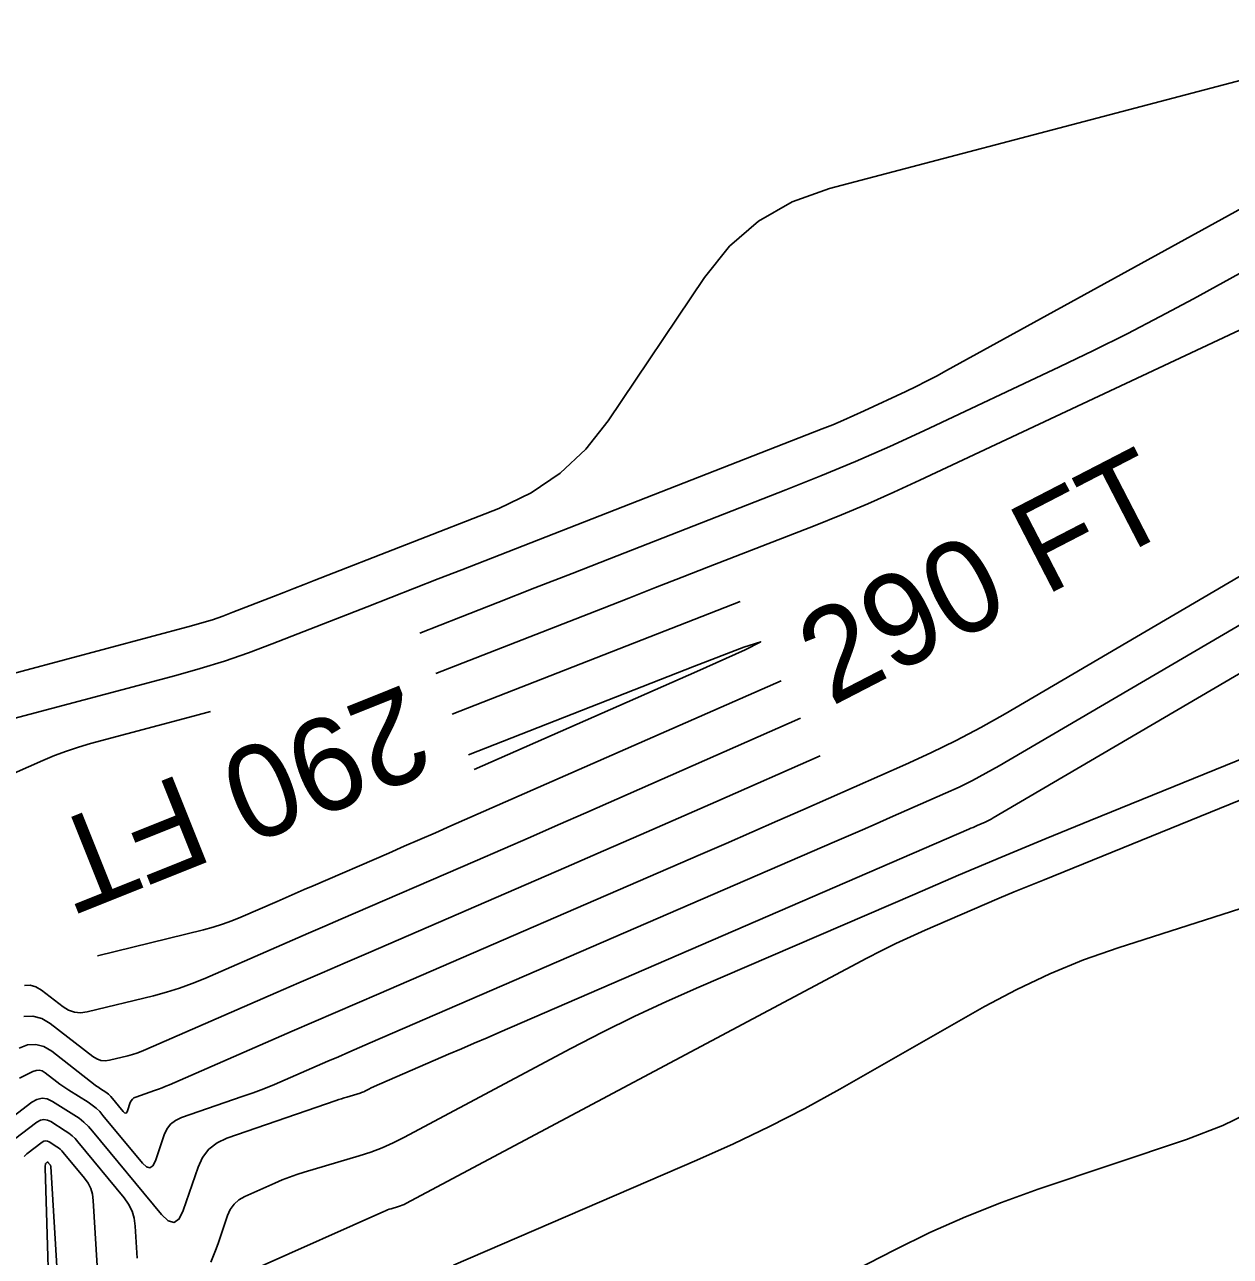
# Model space of a CAD drawing. Extents: x 1768942 to 1774819, y 723037 to 732099.
# Drawn here: x 1771159.5 to 1771237.8, y 724938 to 725018 of the extents above; entities that cross this region are included whole.
import ezdxf

# ---------------------------------------------------------------- set-up
doc = ezdxf.new("R2010")
doc.units = 0
doc.layers.add('R_Contour Annot', color=7, linetype='Continuous')
doc.layers.add('R_Contours', color=7, linetype='Continuous')

msp = doc.modelspace()

# ---------------------------------------------------------------- linework, layer by layer
at = {"layer": 'R_Contours'}
for points in [[(1771252.283, 725017.976), (1771211.803, 725007.343), (1771209.362, 725006.474), (1771207.194, 725005.222), (1771205.298, 725003.586), (1771203.675, 725001.567), (1771197.412, 724992.252), (1771195.972, 724990.415), (1771194.311, 724988.856), (1771192.426, 724987.574), (1771190.32, 724986.569), (1771178.334, 724981.891), (1771177.673, 724981.633), (1771177.013, 724981.375), (1771176.352, 724981.117), (1771175.692, 724980.858), (1771173.05, 724979.825), (1771172.387, 724979.576), (1771171.717, 724979.346), (1771171.041, 724979.135), (1771170.359, 724978.942), (1771153.855, 724974.542)], [(1771158.833, 724972.923), (1771169.339, 724975.724), (1771170.928, 724976.172), (1771172.503, 724976.664), (1771174.063, 724977.2), (1771175.609, 724977.78), (1771181.763, 724980.188), (1771183.302, 724980.79), (1771184.841, 724981.392), (1771186.38, 724981.993), (1771187.919, 724982.594), (1771211.322, 724991.729), (1771212.013, 724992.005), (1771212.699, 724992.293), (1771213.38, 724992.592), (1771214.056, 724992.903), (1771216.752, 724994.169), (1771217.423, 724994.491), (1771218.089, 724994.823), (1771218.749, 724995.166), (1771219.405, 724995.519), (1771255.159, 725015.181)], [(1771254.458, 725010.646), (1771235.427, 725000.181), (1771233.283, 724999.024), (1771231.121, 724997.902), (1771228.942, 724996.814), (1771226.744, 724995.761), (1771217.921, 724991.617), (1771215.707, 724990.599), (1771213.477, 724989.619), (1771211.231, 724988.677), (1771208.968, 724987.772), (1771197.504, 724983.297), (1771195.086, 724982.354), (1771192.669, 724981.409), (1771190.252, 724980.464), (1771187.835, 724979.518), (1771185.181, 724978.48)], [(1771239.857, 724998.818), (1771217.665, 724988.395), (1771215.981, 724987.621), (1771214.285, 724986.876), (1771212.576, 724986.159), (1771210.856, 724985.471), (1771203.949, 724982.775), (1771202.223, 724982.101), (1771200.496, 724981.427), (1771198.77, 724980.752), (1771197.044, 724980.077), (1771186.235, 724975.846)], [(1771156.227, 724945.148), (1771159.995, 724948.02), (1771160.323, 724948.209), (1771160.657, 724948.283), (1771160.995, 724948.24), (1771161.339, 724948.08), (1771162.725, 724947.21), (1771163.061, 724946.98), (1771163.375, 724946.726), (1771163.668, 724946.447), (1771163.939, 724946.144), (1771168.41, 724940.73), (1771168.852, 724940.317), (1771169.237, 724940.223), (1771169.563, 724940.448), (1771169.831, 724940.99), (1771170.786, 724943.798), (1771171.083, 724944.442), (1771171.495, 724944.971), (1771172.022, 724945.386), (1771172.665, 724945.686), (1771179.757, 724948.137), (1771179.928, 724948.195), (1771180.099, 724948.251), (1771180.271, 724948.305), (1771180.443, 724948.357), (1771181.321, 724948.619), (1771181.4, 724948.645), (1771181.477, 724948.674), (1771181.553, 724948.708), (1771181.627, 724948.745), (1771181.921, 724948.901), (1771181.995, 724948.939), (1771182.069, 724948.976), (1771182.144, 724949.011), (1771182.22, 724949.045), (1771187.062, 724951.132), (1771187.894, 724951.491), (1771188.726, 724951.85), (1771189.558, 724952.21), (1771190.39, 724952.57), (1771220.852, 724965.75), (1771220.984, 724965.807), (1771221.117, 724965.865), (1771221.249, 724965.923), (1771221.381, 724965.981), (1771221.909, 724966.213), (1771222.04, 724966.273), (1771222.169, 724966.336), (1771222.296, 724966.403), (1771222.422, 724966.474), (1771261.237, 724989.205)], [(1771159.189, 724949.581), (1771160.055, 724950.015), (1771160.266, 724950.091), (1771160.471, 724950.103), (1771160.67, 724950.051), (1771160.862, 724949.936), (1771161.62, 724949.347), (1771161.811, 724949.202), (1771162.006, 724949.062), (1771162.204, 724948.927), (1771162.405, 724948.797), (1771163.65, 724948.016), (1771163.917, 724947.833), (1771164.166, 724947.631), (1771164.399, 724947.41), (1771164.614, 724947.169), (1771167.172, 724944.072), (1771167.435, 724943.826), (1771167.664, 724943.77), (1771167.858, 724943.903), (1771168.018, 724944.226), (1771168.587, 724945.898), (1771168.763, 724946.281), (1771169.008, 724946.596), (1771169.322, 724946.843), (1771169.705, 724947.022), (1771173.649, 724948.385), (1771174.357, 724948.637), (1771175.06, 724948.903), (1771175.758, 724949.183), (1771176.451, 724949.477), (1771179.21, 724950.679), (1771179.9, 724950.979), (1771180.591, 724951.279), (1771181.281, 724951.578), (1771181.971, 724951.877), (1771212.131, 724964.927), (1771213.031, 724965.317), (1771213.931, 724965.709), (1771214.83, 724966.102), (1771215.729, 724966.496), (1771219.322, 724968.076), (1771220.214, 724968.483), (1771221.093, 724968.916), (1771221.959, 724969.374), (1771222.812, 724969.857), (1771251.694, 724986.77)], [(1771242.15, 724984.336), (1771223.202, 724973.24), (1771221.621, 724972.344), (1771220.016, 724971.496), (1771218.387, 724970.694), (1771216.735, 724969.939), (1771210.076, 724967.012), (1771208.411, 724966.281), (1771206.745, 724965.553), (1771205.078, 724964.827), (1771203.41, 724964.104), (1771182.532, 724955.07), (1771181.124, 724954.461), (1771179.716, 724953.85), (1771178.309, 724953.239), (1771176.902, 724952.627), (1771168.944, 724949.161), (1771168.703, 724949.059), (1771168.459, 724948.961), (1771168.214, 724948.868), (1771167.967, 724948.78), (1771166.745, 724948.358), (1771166.622, 724948.3), (1771166.522, 724948.221), (1771166.443, 724948.121), (1771166.387, 724947.998), (1771166.205, 724947.463), (1771166.154, 724947.359), (1771166.092, 724947.317), (1771166.018, 724947.334), (1771165.934, 724947.413), (1771165.115, 724948.405), (1771165.046, 724948.482), (1771164.972, 724948.553), (1771164.892, 724948.617), (1771164.806, 724948.676), (1771164.454, 724948.897), (1771164.367, 724948.953), (1771164.281, 724949.012), (1771164.196, 724949.073), (1771164.113, 724949.135), (1771161.289, 724951.331), (1771160.783, 724951.634), (1771160.26, 724951.77), (1771159.721, 724951.738), (1771159.165, 724951.539)], [(1771187.289, 724973.212), (1771205.998, 724980.535)], [(1771188.343, 724970.578), (1771203.031, 724976.327), (1771206.24, 724977.558), (1771207.334, 724977.91), (1771206.312, 724977.384), (1771203.175, 724975.979), (1771188.724, 724969.626)], [(1771164.253, 724957.532), (1771171.149, 724959.218), (1771171.767, 724959.383), (1771172.376, 724959.574), (1771172.977, 724959.791), (1771173.568, 724960.034), (1771175.917, 724961.057), (1771176.505, 724961.312), (1771177.092, 724961.568), (1771177.68, 724961.823), (1771178.268, 724962.077), (1771183.168, 724964.197), (1771184.18, 724964.636), (1771185.192, 724965.077), (1771186.203, 724965.519), (1771187.213, 724965.962), (1771208.658, 724975.389)], [(1771174.684, 724937.285), (1771182.851, 724940.933), (1771182.967, 724940.982), (1771183.085, 724941.028), (1771183.204, 724941.07), (1771183.325, 724941.108), (1771183.81, 724941.253), (1771183.93, 724941.292), (1771184.048, 724941.337), (1771184.164, 724941.388), (1771184.277, 724941.444), (1771214.225, 724957.371), (1771215.156, 724957.854), (1771216.097, 724958.318), (1771217.047, 724958.763), (1771218.006, 724959.188), (1771221.861, 724960.85), (1771222.825, 724961.263), (1771223.792, 724961.67), (1771224.762, 724962.073), (1771225.733, 724962.47), (1771256.75, 724975.066)], [(1771171.598, 724973.396), (1771170.556, 724973.102), (1771163.811, 724971.304), (1771163.021, 724971.077), (1771162.241, 724970.82), (1771161.471, 724970.533), (1771160.713, 724970.215), (1771157.698, 724968.887)], [(1771159.509, 724955.596), (1771159.889, 724955.618), (1771160.258, 724955.522), (1771160.614, 724955.308), (1771162.018, 724954.217), (1771162.379, 724953.992), (1771162.76, 724953.861), (1771163.162, 724953.825), (1771163.583, 724953.883), (1771167.887, 724954.935), (1771168.742, 724955.164), (1771169.585, 724955.428), (1771170.416, 724955.728), (1771171.235, 724956.064), (1771175.877, 724958.086), (1771176.922, 724958.541), (1771177.967, 724958.995), (1771179.012, 724959.448), (1771180.058, 724959.901), (1771188.775, 724963.673), (1771190.576, 724964.454), (1771192.376, 724965.237), (1771194.174, 724966.023), (1771195.972, 724966.812), (1771209.922, 724972.944)], [(1771159.48, 724953.58), (1771160.067, 724953.615), (1771160.636, 724953.467), (1771161.187, 724953.136), (1771163.956, 724950.984), (1771164.205, 724950.829), (1771164.468, 724950.738), (1771164.745, 724950.713), (1771165.036, 724950.754), (1771166.228, 724951.045), (1771166.524, 724951.124), (1771166.816, 724951.216), (1771167.103, 724951.319), (1771167.387, 724951.436), (1771175.837, 724955.116), (1771177.339, 724955.769), (1771178.842, 724956.422), (1771180.345, 724957.074), (1771181.848, 724957.725), (1771194.689, 724963.281), (1771197.125, 724964.337), (1771199.56, 724965.397), (1771201.993, 724966.46), (1771204.424, 724967.527), (1771211.186, 724970.5)], [(1771171.619, 724937.648), (1771171.797, 724938.069), (1771171.962, 724938.495), (1771172.115, 724938.926), (1771172.7, 724940.662), (1771172.88, 724941.065), (1771173.129, 724941.406), (1771173.445, 724941.685), (1771173.829, 724941.903), (1771175.782, 724942.775), (1771176.25, 724942.975), (1771176.724, 724943.16), (1771177.203, 724943.328), (1771177.688, 724943.482), (1771181.253, 724944.545), (1771182.002, 724944.788), (1771182.737, 724945.069), (1771183.456, 724945.385), (1771184.161, 724945.738), (1771194.996, 724951.5), (1771197.045, 724952.563), (1771199.114, 724953.583), (1771201.203, 724954.561), (1771203.313, 724955.496), (1771217.331, 724961.539), (1771220.171, 724962.754), (1771223.016, 724963.954), (1771225.869, 724965.139), (1771228.727, 724966.309), (1771240.173, 724970.957)], [(1771239.601, 724960.955), (1771230.538, 724958.041), (1771228.297, 724957.256), (1771226.106, 724956.36), (1771223.964, 724955.35), (1771221.871, 724954.229), (1771212.472, 724948.877), (1771210.2, 724947.624), (1771207.896, 724946.437), (1771205.56, 724945.314), (1771203.191, 724944.255), (1771187.386, 724937.454)], [(1771198.216, 724929.319), (1771216.032, 724938.446), (1771218.308, 724939.559), (1771220.621, 724940.585), (1771222.971, 724941.523), (1771225.358, 724942.374), (1771234.979, 724945.602), (1771237.332, 724946.506), (1771239.579, 724947.604)], [(1771158.42, 724945.268), (1771160.325, 724946.72), (1771160.547, 724946.848), (1771160.772, 724946.898), (1771161, 724946.869), (1771161.233, 724946.761), (1771162.168, 724946.173), (1771162.395, 724946.018), (1771162.607, 724945.847), (1771162.805, 724945.658), (1771162.988, 724945.454), (1771165.986, 724941.822), (1771166.28, 724941.407), (1771166.499, 724940.961), (1771166.643, 724940.486), (1771166.711, 724939.982), (1771166.837, 724937.905)], [(1771159.486, 724944.5), (1771159.667, 724944.667), (1771160.655, 724945.42), (1771160.77, 724945.487), (1771160.887, 724945.513), (1771161.006, 724945.498), (1771161.126, 724945.442), (1771161.611, 724945.137), (1771161.729, 724945.056), (1771161.839, 724944.967), (1771161.942, 724944.87), (1771162.037, 724944.763), (1771163.415, 724943.094), (1771163.646, 724942.767), (1771163.818, 724942.417), (1771163.931, 724942.044), (1771163.985, 724941.648), (1771164.37, 724935.292)], [(1771161.969, 724931.594), (1771161.226, 724943.848), (1771161.222, 724943.877), (1771161.214, 724943.904), (1771161.202, 724943.929), (1771161.185, 724943.952), (1771161.085, 724944.073), (1771161.078, 724944.081), (1771161.071, 724944.088), (1771161.063, 724944.094), (1771161.055, 724944.1), (1771161.019, 724944.122), (1771161.011, 724944.126), (1771161.002, 724944.127), (1771160.994, 724944.126), (1771160.985, 724944.121), (1771160.914, 724944.066), (1771160.901, 724944.054), (1771160.891, 724944.04), (1771160.884, 724944.025), (1771160.881, 724944.007), (1771160.867, 724943.874), (1771160.865, 724943.846), (1771160.863, 724943.818), (1771160.862, 724943.789), (1771160.863, 724943.761), (1771161.223, 724931.506)]]:
    msp.add_lwpolyline(points, dxfattribs=at)

# ---------------------------------------------------------------- texts
at = {"layer": 'R_Contour Annot'}
for rotation, p in [(27.33462, (1771211.903, 724973.689)), (201.80946, (1771184.222, 724975.216))]:
    msp.add_text('290 FT', height=6, rotation=rotation, dxfattribs=at).set_placement(p)

doc.saveas('drawing.dxf')
